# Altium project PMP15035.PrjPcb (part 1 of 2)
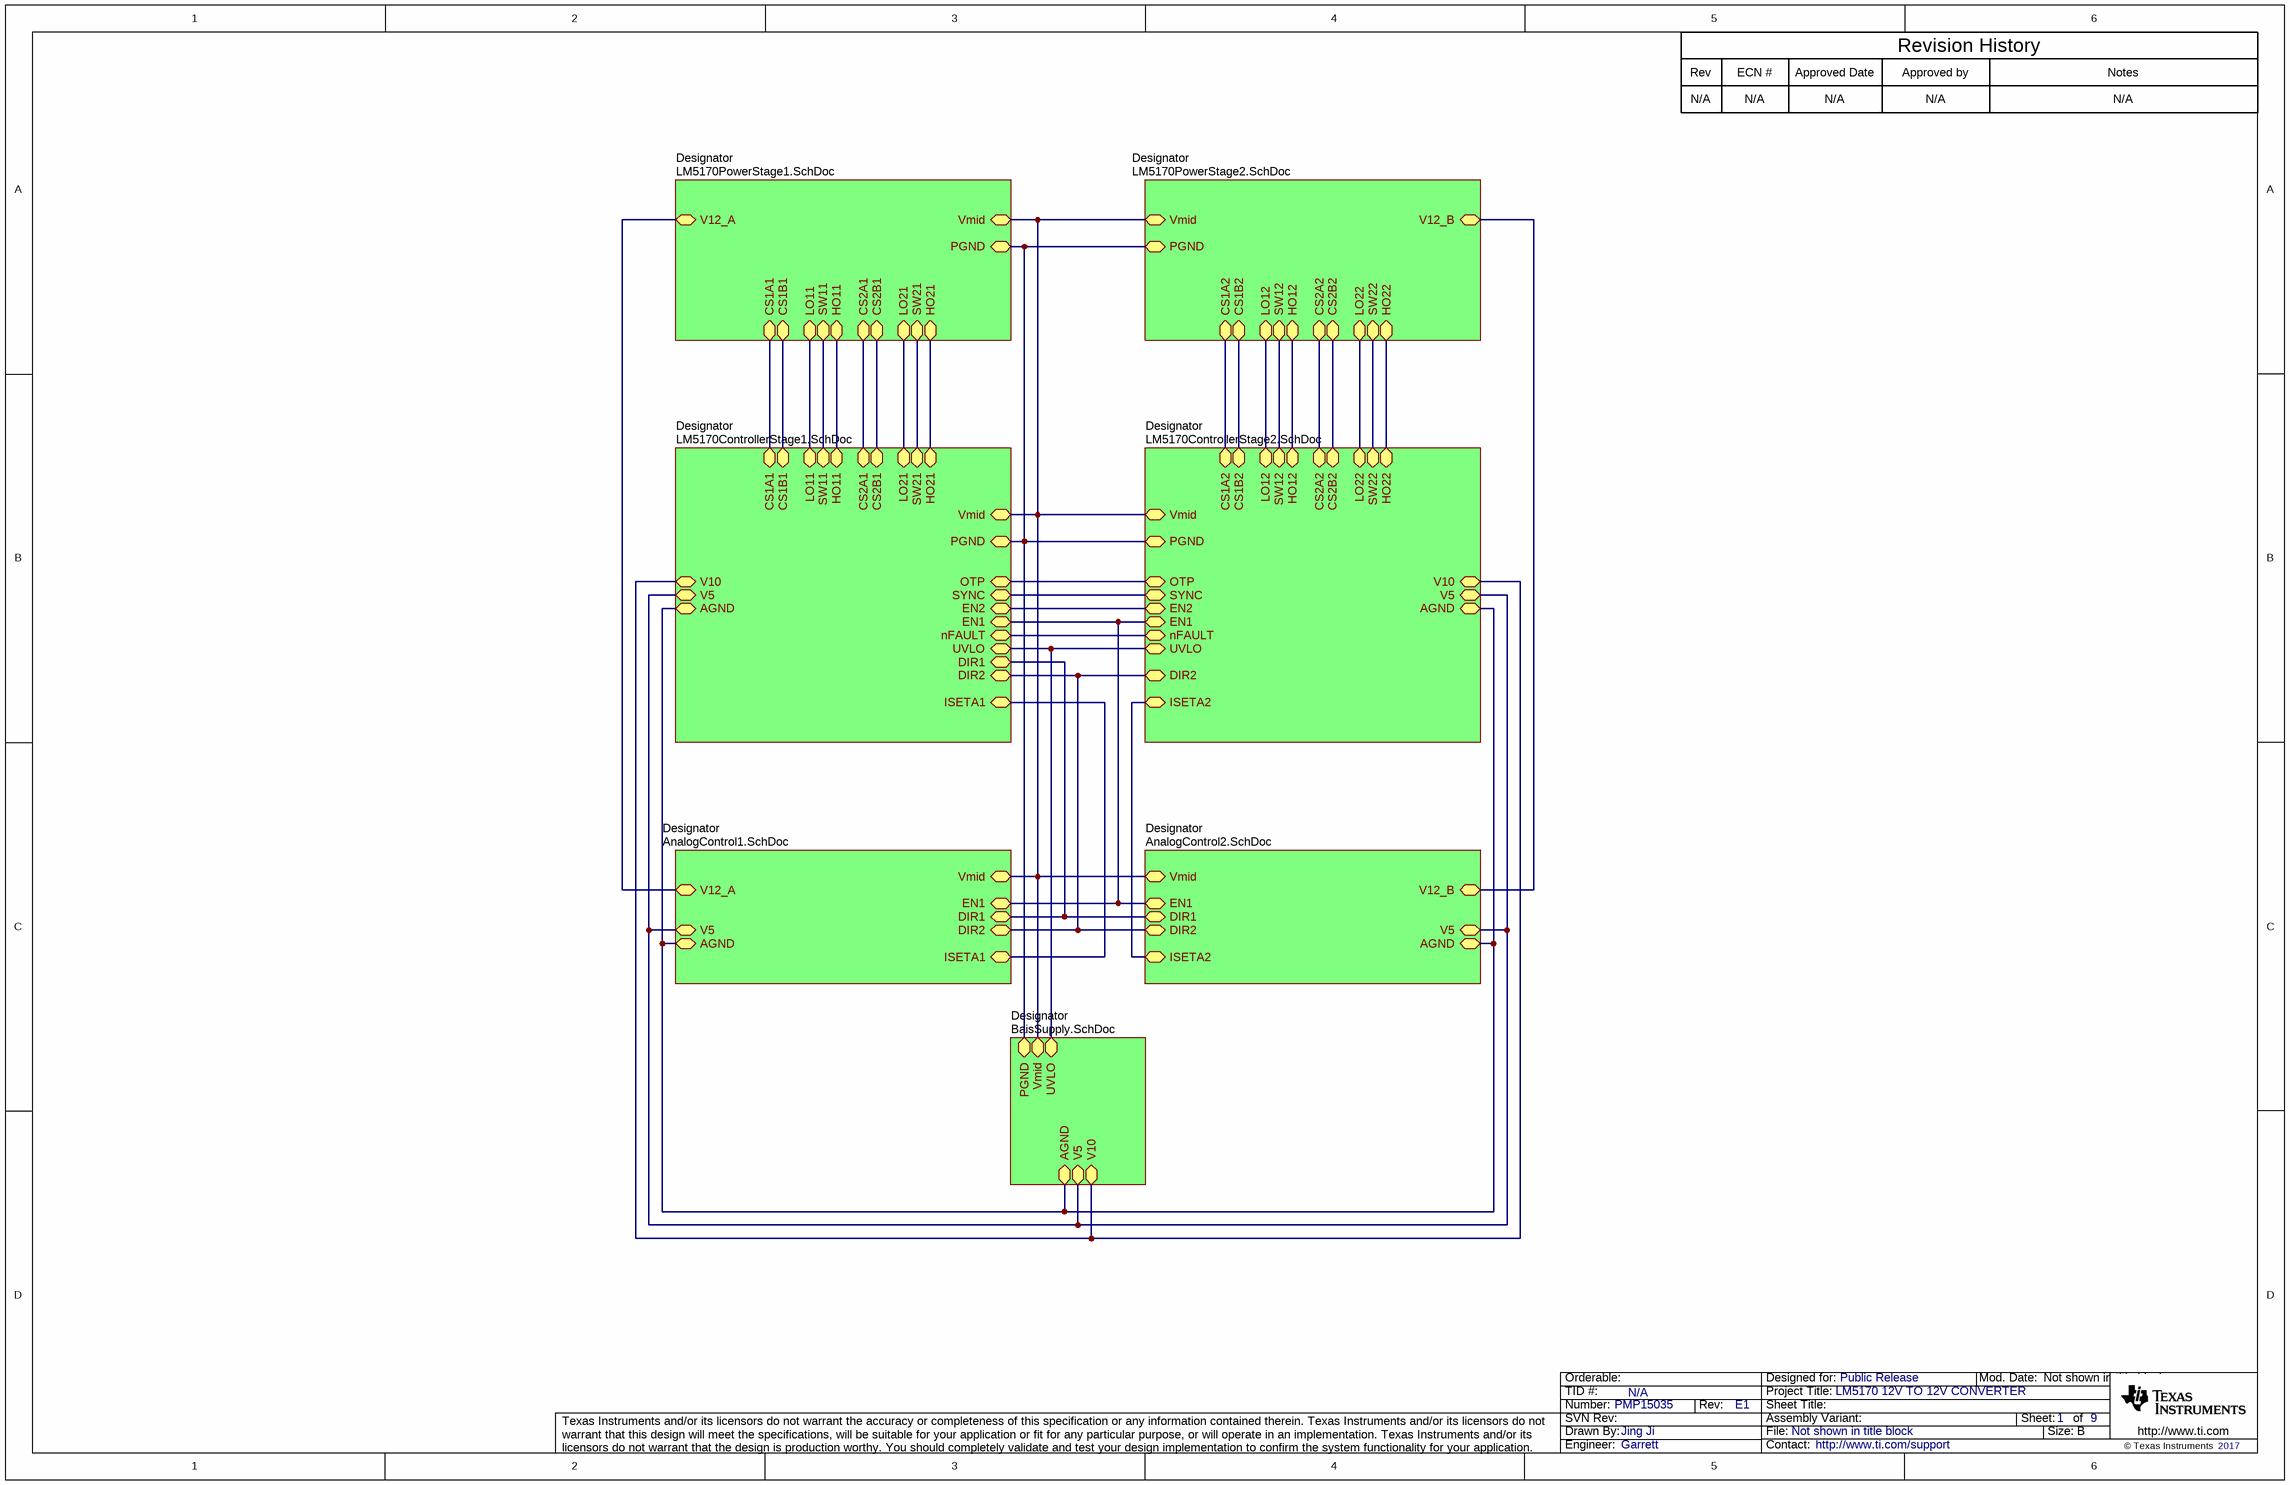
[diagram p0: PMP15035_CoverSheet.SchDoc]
CopyrightYear: 2017; PCB_Layout: Jing Ji; PCB_Rev: E1; PRJ_Customer: Public Release; PRJ_Engineer: Garrett; PRJ_Number: PMP15035; PRJ_Title: LM5170 12V TO 12V CONVERTER; SCH_Rev: E1; TechSupport: http://www.ti.com/support; TID: N/A
8 sheets, 339 parts. Net scope: hierarchical (ports join the sheet entries above them; power ports are global).
Board file: PMP15035_PCB.PcbDoc
Sheets:
  PMP15035_CoverSheet.SchDoc
    Designator = AnalogControl2.SchDoc
    Designator = LM5170PowerStage2.SchDoc
    Designator = LM5170PowerStage1.SchDoc
    Designator = AnalogControl1.SchDoc
    Designator = LM5170ControllerStage1.SchDoc
    Designator = LM5170ControllerStage2.SchDoc
    Designator = BaisSupply.SchDoc

## Sheet PMP15035_CoverSheet.SchDoc
size 431 x 279 mm; Date: Not shown in title block; ApprovedBy: Not shown in title block; CheckedBy: Not shown in title block; Author: Not shown in title block; CompanyName: Not shown in title block; DrawnBy: Jing Ji; Engineer: Not shown in title block; Organization: Not shown in title block; Address1: Not shown in title block; Address2: Not shown in title block; Address3: Not shown in title block; Address4: Not shown in title block; DocumentNumber: 1; Revision: Use project parameter SCH_Rev; SheetNumber: 1; SheetTotal: 9; PageSetup: Record=PageOptions¦CenterHorizontal=True¦CenterVertical=True¦PrintScale=1.00¦XCorrection=1.00¦YCorrection=1.00¦PrintKind=0¦BorderSize=5000000¦LeftOffset=0¦BottomOffset=0¦Orientation=2¦PaperLength=1000¦PaperWidth=1000¦Scale=100¦PaperSource=15¦PrintQuality=600¦MediaType=1¦DitherType=10¦PaperKind=Letter¦PrintScaleMode=1

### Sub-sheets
Designator = AnalogControl2.SchDoc: Vmid, V12_B, AGND, V5, DIR2, ISETA2, DIR1, EN1
Designator = LM5170PowerStage2.SchDoc: V12_B, Vmid, PGND, CS1A2, CS1B2, LO12, SW12, HO12, CS2A2, CS2B2, LO22, SW22, HO22
Designator = LM5170PowerStage1.SchDoc: Vmid, V12_A, PGND, CS1A1, CS1B1, LO11, SW11, HO11, CS2A1, CS2B1, LO21, SW21, HO21
Designator = AnalogControl1.SchDoc: Vmid, V12_A, AGND, V5, DIR1, ISETA1, DIR2, EN1
Designator = LM5170ControllerStage1.SchDoc: CS1A1, CS1B1, LO11, SW11, HO11, CS2A1, CS2B1, LO21, SW21, HO21, Vmid, PGND, V10, AGND, DIR1, ISETA1, DIR2, nFAULT, EN1, EN2, UVLO, SYNC, V5, OTP
Designator = LM5170ControllerStage2.SchDoc: CS1A2, CS1B2, LO12, SW12, HO12, CS2A2, CS2B2, LO22, SW22, HO22, Vmid, PGND, V10, AGND, DIR2, ISETA2, nFAULT, EN1, EN2, SYNC, UVLO, V5, OTP
Designator = BaisSupply.SchDoc: V10, AGND, PGND, Vmid, V5, UVLO

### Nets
AGND: sheet Designator/AGND, sheet Designator/AGND, sheet Designator/AGND, sheet Designator/AGND, sheet Designator/AGND
DIR1: sheet Designator/DIR1, sheet Designator/DIR1, sheet Designator/DIR1
EN1: sheet Designator/EN1, sheet Designator/EN1, sheet Designator/EN1, sheet Designator/EN1
EN2: sheet Designator/EN2, sheet Designator/EN2
nFAULT: sheet Designator/nFAULT, sheet Designator/nFAULT
PGND: sheet Designator/PGND, sheet Designator/PGND, sheet Designator/PGND, sheet Designator/PGND, sheet Designator/PGND
V5: sheet Designator/V5, sheet Designator/V5, sheet Designator/V5, sheet Designator/V5, sheet Designator/V5
V12_A: sheet Designator/V12_A, sheet Designator/V12_A
V12_B: sheet Designator/V12_B, sheet Designator/V12_B
VCC1: sheet Designator/V10, sheet Designator/V10, sheet Designator/V10
Vmid: sheet Designator/Vmid, sheet Designator/Vmid, sheet Designator/Vmid, sheet Designator/Vmid, sheet Designator/Vmid, sheet Designator/Vmid, sheet Designator/Vmid
CS1A1: sheet Designator/CS1A1, sheet Designator/CS1A1
CS1A2: sheet Designator/CS1A2, sheet Designator/CS1A2
CS1B1: sheet Designator/CS1B1, sheet Designator/CS1B1
CS1B2: sheet Designator/CS1B2, sheet Designator/CS1B2
CS2A1: sheet Designator/CS2A1, sheet Designator/CS2A1
CS2A2: sheet Designator/CS2A2, sheet Designator/CS2A2
CS2B1: sheet Designator/CS2B1, sheet Designator/CS2B1
CS2B2: sheet Designator/CS2B2, sheet Designator/CS2B2
DIR2: sheet Designator/DIR2, sheet Designator/DIR2, sheet Designator/DIR2, sheet Designator/DIR2
HO11: sheet Designator/HO11, sheet Designator/HO11
HO12: sheet Designator/HO12, sheet Designator/HO12
HO21: sheet Designator/HO21, sheet Designator/HO21
HO22: sheet Designator/HO22, sheet Designator/HO22
ISETA1: sheet Designator/ISETA1, sheet Designator/ISETA1
ISETA2: sheet Designator/ISETA2, sheet Designator/ISETA2
LO11: sheet Designator/LO11, sheet Designator/LO11
LO12: sheet Designator/LO12, sheet Designator/LO12
LO21: sheet Designator/LO21, sheet Designator/LO21
LO22: sheet Designator/LO22, sheet Designator/LO22
OTP: sheet Designator/OTP, sheet Designator/OTP
SW11: sheet Designator/SW11, sheet Designator/SW11
SW12: sheet Designator/SW12, sheet Designator/SW12
SW21: sheet Designator/SW21, sheet Designator/SW21
SW22: sheet Designator/SW22, sheet Designator/SW22
SYNC: sheet Designator/SYNC, sheet Designator/SYNC
UVLO: sheet Designator/UVLO, sheet Designator/UVLO, sheet Designator/UVLO

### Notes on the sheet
- Rev
- N/A
- ECN #
- Approved Date
- Approved by
- Revision History
- Notes

## Sheet AnalogControl2.SchDoc
size 431 x 279 mm; Date: Not shown in title block; ApprovedBy: Not shown in title block; CheckedBy: Not shown in title block; Author: Not shown in title block; CompanyName: Not shown in title block; Engineer: Not shown in title block; Organization: Not shown in title block; Address1: Not shown in title block; Address2: Not shown in title block; Address3: Not shown in title block; Address4: Not shown in title block; DocumentNumber: 7; Revision: Use project parameter SCH_Rev; SheetNumber: 7; SheetTotal: 9; PageSetup: Record=PageOptions¦CenterHorizontal=True¦CenterVertical=True¦PrintScale=1.00¦XCorrection=1.00¦YCorrection=1.00¦PrintKind=0¦BorderSize=5000000¦LeftOffset=0¦BottomOffset=0¦Orientation=2¦PaperLength=1000¦PaperWidth=1000¦Scale=100¦PaperSource=15¦PrintQuality=600¦MediaType=1¦DitherType=10¦PaperKind=Letter¦PrintScaleMode=1
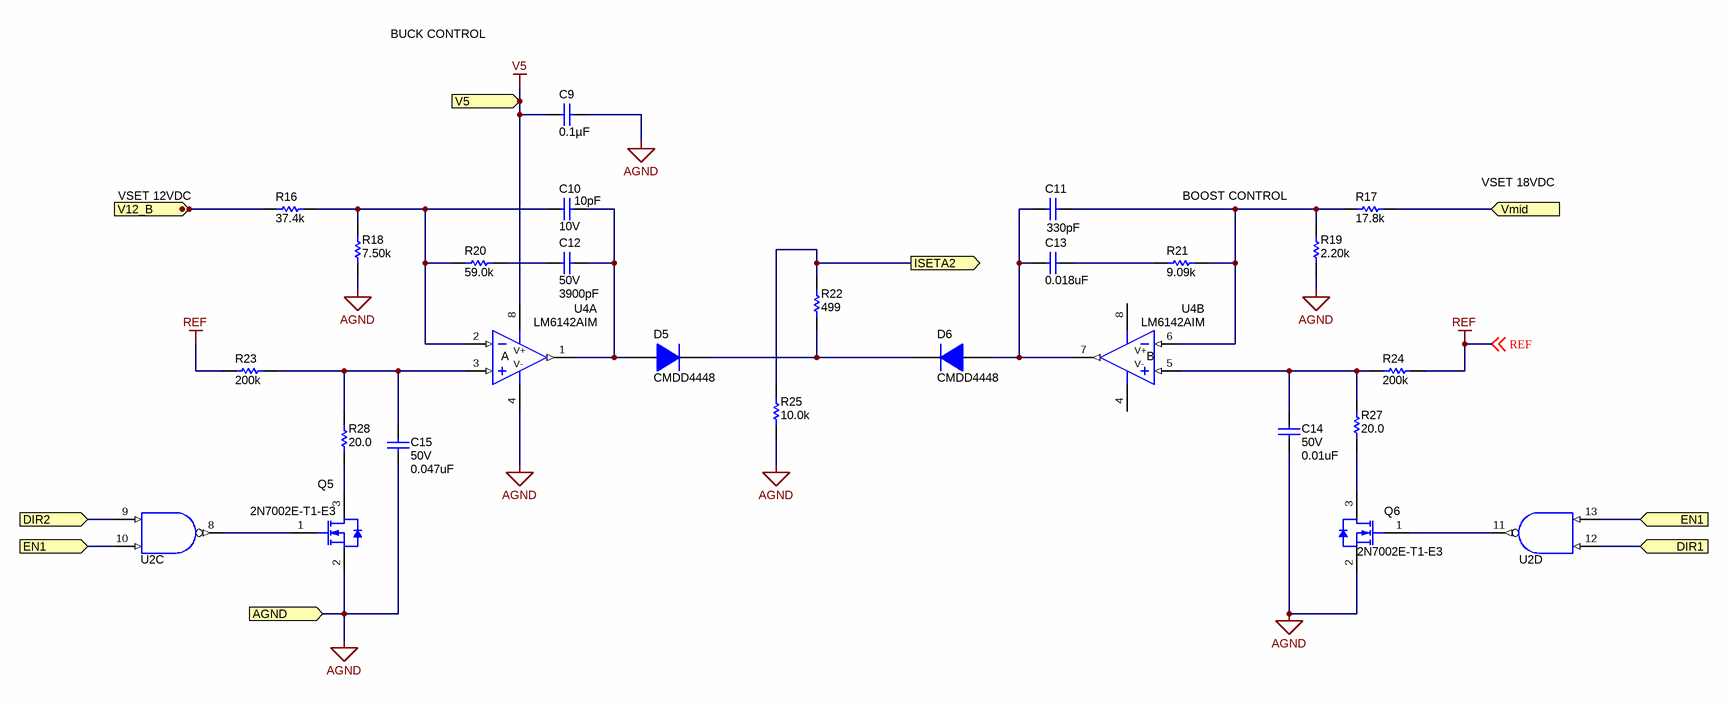
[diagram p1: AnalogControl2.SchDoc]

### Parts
C9  ValueDisplayed: 0.1µF  [0603L]  (hidden comment: GRM188R72A104KA35D)
C10  VDC_V: 10V  ValueDisplayed: 10pF  [0603]  (hidden comment: 0603ZC100KAT2A)
C11  ValueDisplayed: 330pF  [0603]  (hidden comment: C0603C331J5GACTU)
C12  VDC_V: 50V  ValueDisplayed: 3900pF  [0603]  (hidden comment: GRM188R71H392KA01D)
C13  ValueDisplayed: 0.018uF  [0603]  (hidden comment: GRM188R71H183KA01D)
C14  VDC_V: 50V  ValueDisplayed: 0.01uF  [0805_HV]  (hidden comment: 885012207092)
C15  VDC_V: 50V  ValueDisplayed: 0.047uF  [0805_HV]  (hidden comment: 08055C473KAT2A)
D5  CMDD4448  [sod-323]
D6  CMDD4448  [sod-323]
Q5  2N7002E-T1-E3  [SOT-23]
Q6  2N7002E-T1-E3  [SOT-23]
R16  ValueDisplayed: 37.4k  [0603L]  (hidden comment: CRCW060337K4FKEA)
R17  ValueDisplayed: 17.8k  [0603L]  (hidden comment: RC0603FR-0717K8L)
R18  ValueDisplayed: 7.50k  [0603]  (hidden comment: RC0603FR-077K5L)
R19  ValueDisplayed: 2.20k  [0603]  (hidden comment: RC0603FR-072K2L)
R20  ValueDisplayed: 59.0k  [0603]  (hidden comment: RC0603FR-0759KL)
R21  ValueDisplayed: 9.09k  [0603]  (hidden comment: RC0603FR-079K09L)
R22  ValueDisplayed: 499  [0603]  (hidden comment: RC0603FR-07499RL)
R23  ValueDisplayed: 200k  [0603]  (hidden comment: RC0603FR-07200KL)
R24  ValueDisplayed: 200k  [0603]  (hidden comment: RC0603FR-07200KL)
R25  ValueDisplayed: 10.0k  [0603L]  (hidden comment: CRCW060310K0FKEA)
R27  ValueDisplayed: 20.0  [0603L]  (hidden comment: CRCW060320R0FKEA)
R28  ValueDisplayed: 20.0  [0603L]  (hidden comment: CRCW060320R0FKEA)
U2  SN74LV00ADR  [D0014A_N]  (value not drawn)  (parts C,D of 5)
U4  LM6142AIM  [D0008A_N]  (parts A,B of 2)

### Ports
AGND, DIR1, DIR2, EN1, ISETA2, V5, V12_B, Vmid

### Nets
AGND: C9.2 C14.2 C15.2 Q5.2(S) Q6.2(S) R18.1 R19.1 R25.2 U4.4(V-) ; port AGND
DIR1: U2.12(4A) ; port DIR1
EN1: U2.10(3B) U2.13(4B) ; port EN1
REF: R23.2 R24.1 ; off-sheet REF
V5: C9.1 U4.8(V+) ; port V5
V12_B: R16.1 ; port V12_B
Vmid: R17.2 ; port Vmid
DIR2: U2.9(3A) ; port DIR2
ISETA2: R22.2 R25.1 ; port ISETA2
NetC10_1: C10.1 C12.1 D5.2(A) U4.1(OUT)
NetC10_2: C10.2 R16.2 R18.2 R20.2 U4.2(IN-)
NetC11_1: C11.1 R17.1 R19.2 R21.1 U4.6(IN-)
NetC11_2: C11.2 C13.1 D6.2(A) U4.7(OUT)
NetC12_2: C12.2 R20.1
NetC13_2: C13.2 R21.2
NetC14_1: C14.1 R24.2 R27.2 U4.5(IN+)
NetC15_1: C15.1 R23.1 R28.2 U4.3(IN+)
NetD5_1: D5.1(K) D6.1(K) R22.1
NetQ5_1: Q5.1(G) U2.8(3Y)
NetQ5_3: Q5.3(D) R28.1
NetQ6_1: Q6.1(G) U2.11(4Y)
NetQ6_3: Q6.3(D) R27.1

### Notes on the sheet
- BUCK CONTROL
- VSET 12VDC
- BOOST CONTROL
- VSET 18VDC

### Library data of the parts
C9 = GRM188R72A104KA35D: CAP, CERM, 0.1 µF, 100 V, +/- 10%, X7R, 0603; Manufacturer: MuRata; Polarized: N; CompType: Capacitor; Value: 0.1uF; U/M: EA; Cap_F: 0.0000001; Tolerance_%: 10; Value1: Unknown; VDC_V: 100; Value2: 100V; TaMin_C: -55; TaMax_C: 125; Cap_Case: 0603; AEC Category: Q200
C10 = CMP-0006811-4: CAP, CERM, 10 pF, 10 V, +/- 10%, X7R, 0603; Manufacturer: AVX; TaMin_C: -55°C; Polarized: N; SizeAreaWB_mm2: 4.68; Value1: Unknown; U/M: EA; Value: 10pF; TaMax_C: 125°C; SizeZ_mm: 1; SizeX_mm: 1.6; SizeY_mm: 0.8; SizeArea_mm2: 1.28; CompType: Capacitor; AEC Category: Q200
C11 = CMP-0006920-4: CAP, CERM, 330 pF, 50 V, +/- 5%, C0G/NP0, 0603; Manufacturer: Kemet; TaMin_C: -55°C; Polarized: N; SizeAreaWB_mm2: 4.68; Value1: Unknown; U/M: EA; Value: 330pF; TaMax_C: 125°C; SizeZ_mm: 1; SizeX_mm: 1.6; SizeY_mm: 0.8; Value2: 50V; SizeArea_mm2: 1.28; CompType: Capacitor; AEC Category: Q200
C12 = CMP-0007453-4: CAP, CERM, 3900 pF, 50 V, +/- 10%, X7R, 0603; Manufacturer: MuRata; TaMin_C: -55°C; Polarized: N; SizeAreaWB_mm2: 4.68; Value1: Unknown; U/M: EA; Value: 3900pF; TaMax_C: 125°C; SizeZ_mm: 1; SizeX_mm: 1.6; SizeY_mm: 0.8; SizeArea_mm2: 1.28; CompType: Capacitor; Cap_F: 3.9nF; AEC Category: Q200
C13 = CMP-0007440-5: CAP, CERM, 0.018 uF, 50 V, +/- 10%, X7R, 0603; Manufacturer: MuRata; TaMin_C: -55°C; Polarized: N; SizeAreaWB_mm2: 4.68; Value1: Unknown; U/M: EA; TaMax_C: 125°C; SizeZ_mm: 1; SizeX_mm: 1.6; SizeY_mm: 0.8; Value2: 50V; SizeArea_mm2: 1.28; CompType: Capacitor; Cap_F: 18nF; AEC Category: Q200
C14 = CMP-0007694-2: CAP, CERM, 0.01 uF, 50 V, +/- 10%, X7R, 0805; Manufacturer: Wurth Elektronik; TaMin_C: -55°C; Polarized: N; SizeAreaWB_mm2: 6.75; Value1: Unknown; U/M: EA; Value: 0.01uF; TaMax_C: 125°C; SizeZ_mm: 1.45; SizeX_mm: 2; SizeY_mm: 1.25; Cap_Case: 0805; SizeArea_mm2: 2.5; CompType: Capacitor; Cap_F: 10nF; AEC Category: Q200
C15 = CMP-0007659-2: CAP, CERM, 0.047 uF, 50 V, +/- 10%, X7R, 0805; Manufacturer: AVX; TaMin_C: -55°C; ESR_ohm: 0.035; Polarized: N; SizeAreaWB_mm2: 6.75; Value1: 0.035 ohm; U/M: EA; TaMax_C: 125°C; SizeZ_mm: 1.45; SizeX_mm: 2; SizeY_mm: 1.25; Cap_Case: 0805; SizeArea_mm2: 2.5; CompType: Capacitor; Cap_F: 47nF; AEC Category: Q200
D5 D6 = CMDD4448: Diode, Ultrafast, 75 V, 0.25 A, SOD-323; Manufacturer: Central Semiconductor; U/M: EA; Vf_V: 1.2; Value: 75V; Value1: 0.25A; Value2: 1.2V; Io_A: 0.25; Vr_V: 75; TJmax_C: 175
Q5 Q6 = 2N7002E-T1-E3: MOSFET, N-CH, 60 V, 0.24 A, SOT-23; Manufacturer: Vishay-Siliconix; Alternate Manufacturer: None; U/M: EA; ChType: N; Value: 60V; VdsMax_V: 60; Value1: 1.8 ohm; Rdson45_ohm: 1.8; Value2: 0.4 nC; QgTyp_nC: 0.4; Vgs_V: 20; IdsMax_A: 0.24
R16 = CMP-0022360-3: RES, 37.4 k, 1%, 0.1 W, 0603; Manufacturer: Vishay-Dale; Power_W: 100mW; TempCo: 100 ppm/C; Value_Code: 37k4; U/M: EA; Value: 37.4k; EIA_Code: E96; SizeX_mm: 1.6; SizeY_mm: 0.8; SizeZ_mm: 1; Value2: 0.1W; SizeArea_mm2: 1.28; CompType: Resistor; VDC_V: 75V; AEC Category: Q200
R17 = CMP-0022841-3: RES, 17.8 k, 1%, 0.1 W, 0603; Manufacturer: Yageo America; Power_W: 100mW; TempCo: 200 ppm/C; Value_Code: 17k8; U/M: EA; Value: 17.8k; EIA_Code: E96; SizeX_mm: 1.6; SizeY_mm: 0.8; SizeZ_mm: 1; Value2: 0.1W; SizeArea_mm2: 1.28; CompType: Resistor; VDC_V: 150V; AEC Category: Q200
R18 = CMP-0023279-3: RES, 7.50 k, 1%, 0.1 W, 0603; Manufacturer: Yageo America; Power_W: 100mW; TempCo: 200 ppm/C; Value_Code: 7k50; U/M: EA; Value: 7.50k; EIA_Code: E96; Res_ohm: 7.5k; SizeX_mm: 1.6; SizeY_mm: 0.8; SizeZ_mm: 1; Value2: 0.1W; SizeArea_mm2: 1.28; CompType: Resistor; VDC_V: 150V; AEC Category: Q200
R19 = CMP-0022986-3: RES, 2.20 k, 1%, 0.1 W, 0603; Manufacturer: Yageo America; Power_W: 100mW; TempCo: 200 ppm/C; Value_Code: 2k20; U/M: EA; Value: 2.20k; Res_ohm: 2.2k; SizeX_mm: 1.6; SizeY_mm: 0.8; SizeZ_mm: 1; Value2: 0.1W; SizeArea_mm2: 1.28; CompType: Resistor; VDC_V: 150V; AEC Category: Q200
R20 = CMP-0023195-3: RES, 59.0 k, 1%, 0.1 W, 0603; Manufacturer: Yageo America; Power_W: 100mW; TempCo: 200 ppm/C; Value_Code: 59k0; U/M: EA; Value: 59.0k; EIA_Code: E96; Res_ohm: 59k; SizeX_mm: 1.6; SizeY_mm: 0.8; SizeZ_mm: 1; Value2: 0.1W; SizeArea_mm2: 1.28; CompType: Resistor; VDC_V: 150V; AEC Category: Q200
R21 = CMP-0023332-3: RES, 9.09 k, 1%, 0.1 W, 0603; Manufacturer: Yageo America; Power_W: 100mW; TempCo: 200 ppm/C; Value_Code: 9k09; U/M: EA; Value: 9.09k; EIA_Code: E96; SizeX_mm: 1.6; SizeY_mm: 0.8; SizeZ_mm: 1; Value2: 0.1W; SizeArea_mm2: 1.28; CompType: Resistor; VDC_V: 150V; AEC Category: Q200
R22 = CMP-0023141-3: RES, 499, 1%, 0.1 W, 0603; Manufacturer: Yageo America; Power_W: 100mW; TempCo: 200 ppm/C; Value_Code: 499R; U/M: EA; Value: 499; EIA_Code: E96; SizeX_mm: 1.6; SizeY_mm: 0.8; SizeZ_mm: 1; Value2: 0.1W; SizeArea_mm2: 1.28; CompType: Resistor; VDC_V: 150V; AEC Category: Q200
R23 R24 = CMP-0022901-2: RES, 200 k, 1%, 0.1 W, 0603; Manufacturer: Yageo America; Power_W: 100mW; TempCo: 200 ppm/C; U/M: EA; Value: 200k; EIA_Code: E96; SizeX_mm: 1.6; SizeY_mm: 0.8; SizeZ_mm: 1; Value2: 0.1W; CompType: Resistor; VDC_V: 150V; AEC Category: Q200; SizeArea_mm2: 1.28
R25 = CRCW060310K0FKEA: RES, 10.0 k, 1%, 0.1 W, 0603; Manufacturer: Vishay-Dale; CompType: Resistor; Value: 10.0k; Res_ohm: 10000; Value_Code: 10k0; Tolerance_%: 1; Power_W: 0.1; Value2: 0.1W; VDC_V: 75; TempCo: 100 ppm/C; EIA_Code: E96; U/M: EA
R27 R28 = CRCW060320R0FKEA: RES, 20.0, 1%, 0.1 W, 0603; Manufacturer: Vishay-Dale; CompType: Resistor; Value: 20.0; Res_ohm: 20; Value_Code: 20R0; Tolerance_%: 1; Power_W: 0.1; Value2: 0.1W; VDC_V: 75; TempCo: 100 ppm/C; EIA_Code: E96; U/M: EA
U2 = CMP-0052884-1: Quadruple 2-Input Positive-NAND Gates, D0014A, LARGE T&R; Manufacturer: Texas Instruments; Output Drive (IOL/IOH)(Max)(mA): 50/-50; Rating: Catalog; F @ Nom Voltage(Max)(Mhz): 70; tpd @ Nom Voltage(Max)(ns): 20,13,8.5; ICC @ Nom Voltage(Max)(mA): 0.02; Output Type: TTL; Technology Family: LV-A; Bits(#): 4; Schmitt Trigger: No; VCC(Min)(V): 2; Voltage(Nom)(V): 2.5,3.3,5; VCC(Max)(V): 5.5
U4 = LM6142AIM: 17MHz Rail-to-Rail Input and Output Op Amp, D0008A; Manufacturer: Texas Instruments; CompType: OpAmp IC

## Sheet LM5170PowerStage2.SchDoc
size 431 x 279 mm; Date: Not shown in title block; ApprovedBy: Not shown in title block; CheckedBy: Not shown in title block; Author: Not shown in title block; CompanyName: Not shown in title block; Engineer: Not shown in title block; Organization: Not shown in title block; Address1: Not shown in title block; Address2: Not shown in title block; Address3: Not shown in title block; Address4: Not shown in title block; DocumentNumber: 3; Revision: Use project parameter SCH_Rev; SheetNumber: 3; SheetTotal: 9; PageSetup: Record=PageOptions¦CenterHorizontal=True¦CenterVertical=True¦PrintScale=1.00¦XCorrection=1.00¦YCorrection=1.00¦PrintKind=0¦BorderSize=5000000¦LeftOffset=0¦BottomOffset=0¦Orientation=2¦PaperLength=1000¦PaperWidth=1000¦Scale=100¦PaperSource=15¦PrintQuality=600¦MediaType=1¦DitherType=10¦PaperKind=Letter¦PrintScaleMode=1
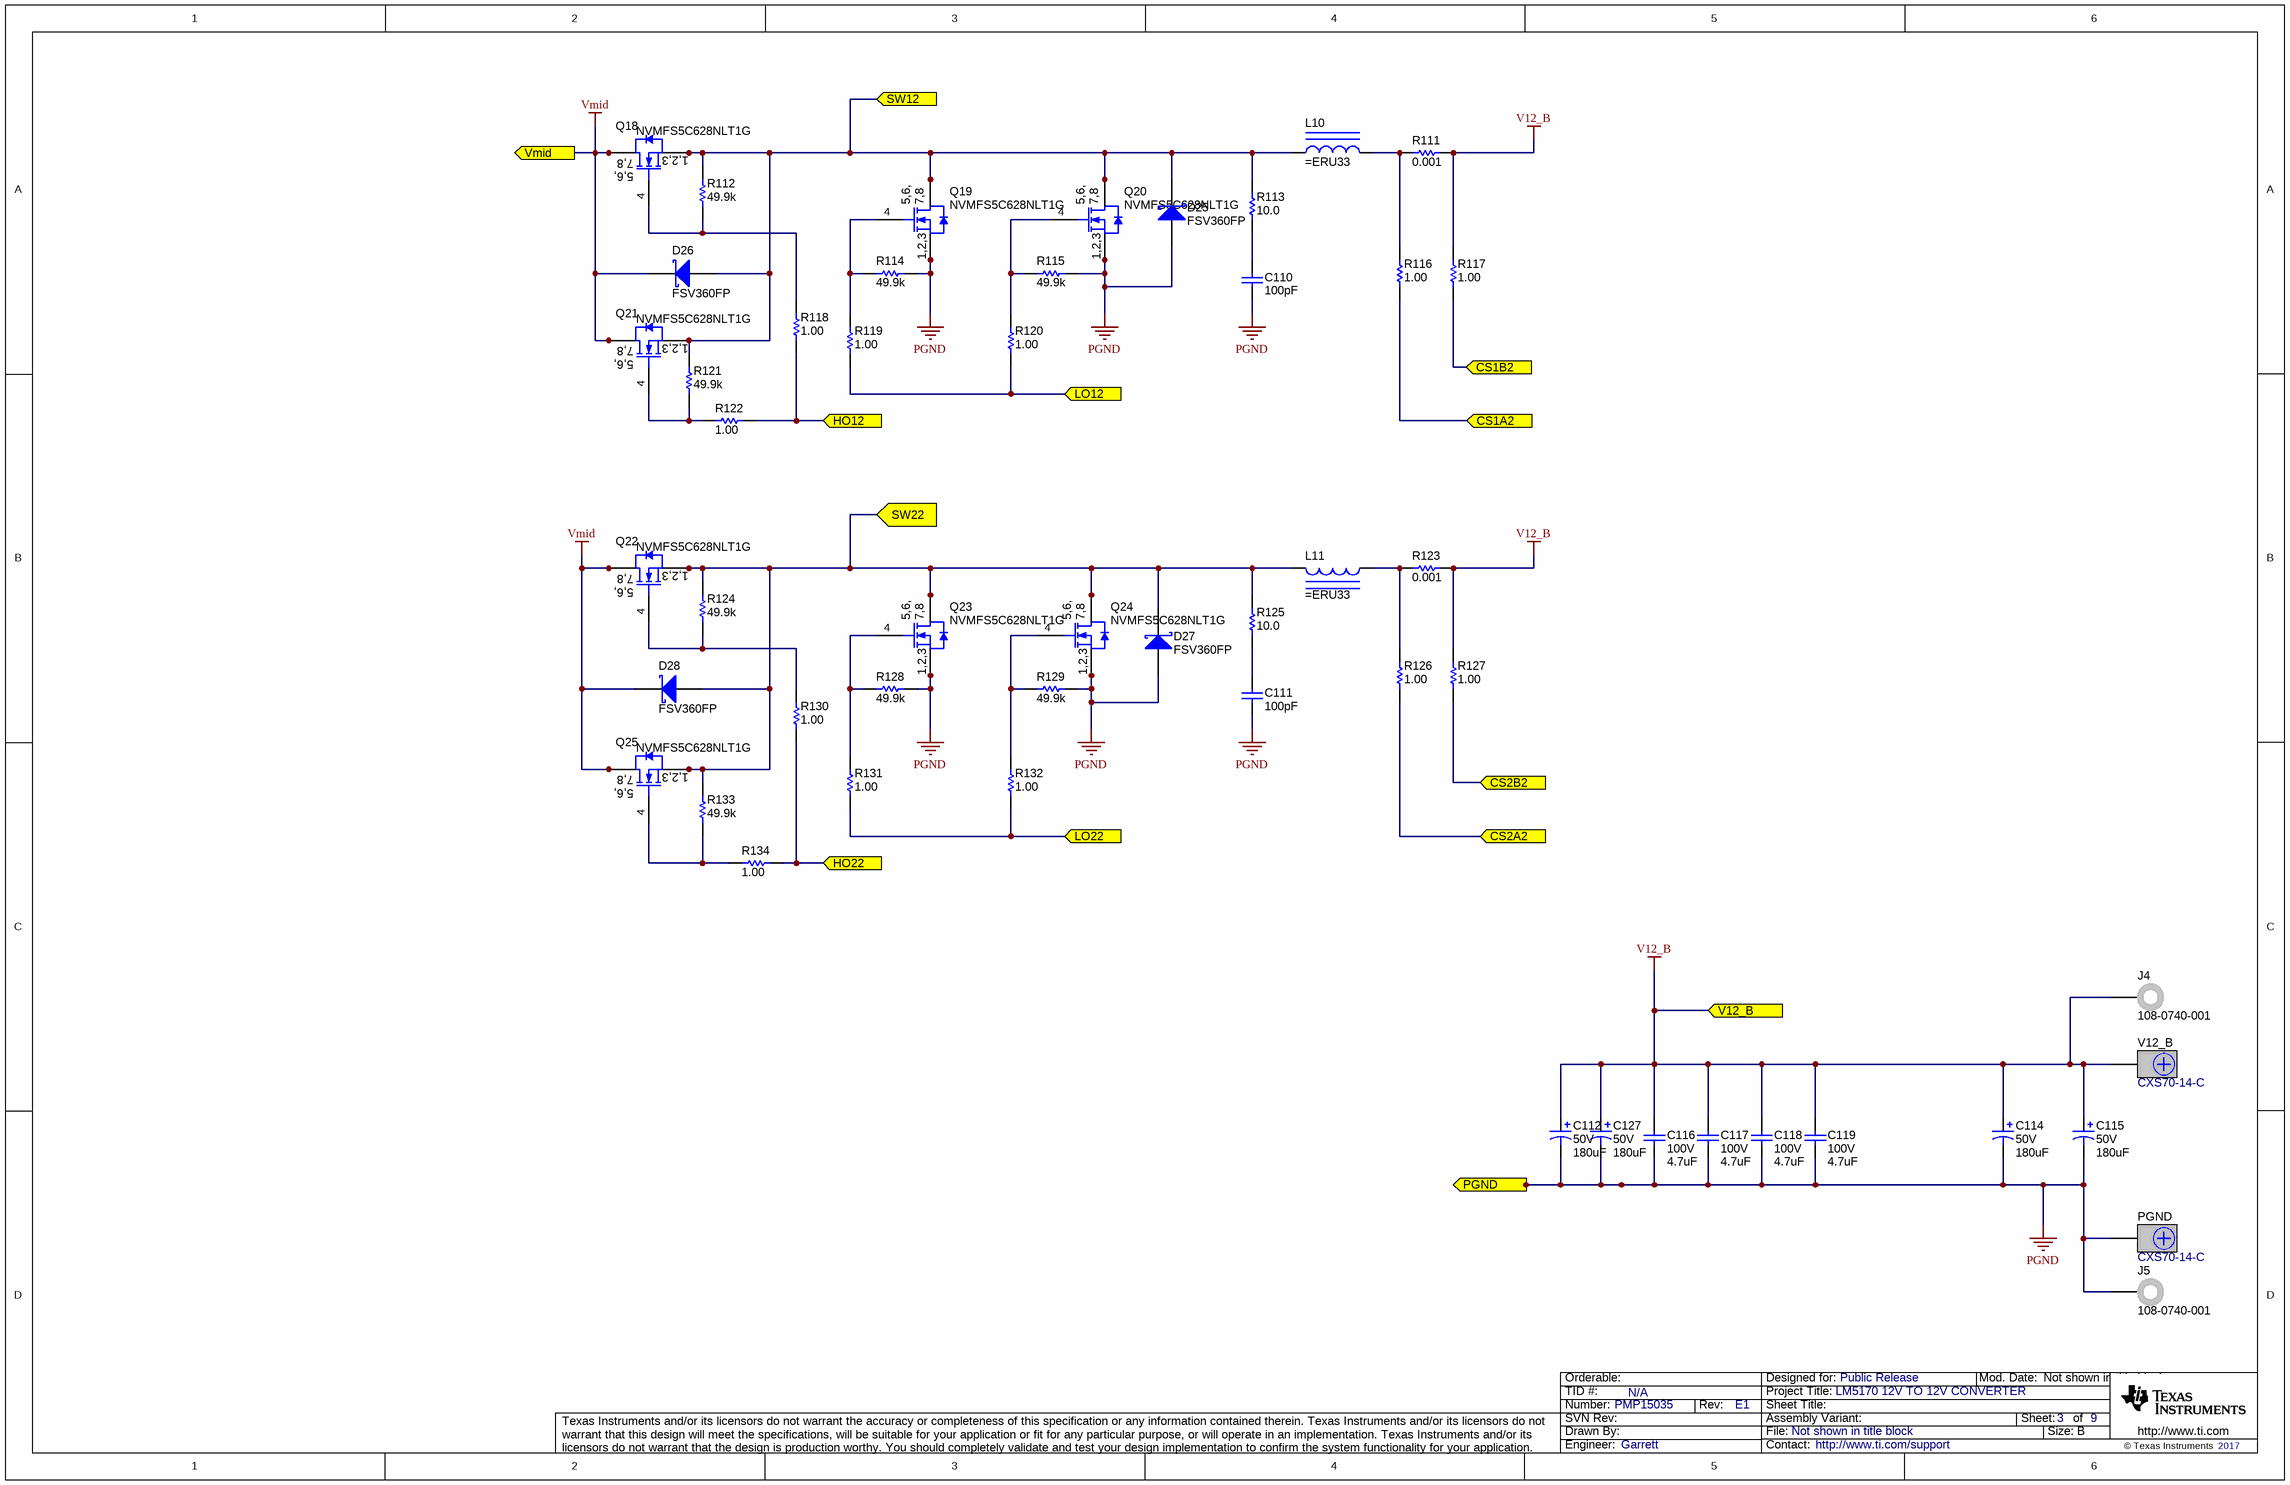
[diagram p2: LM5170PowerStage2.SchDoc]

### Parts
(Parts that share a designator on the sheet are numbered #1, #2 ... from top to bottom, then left to right.)
C110  ValueDisplayed: 100pF  [0805_HV]  (hidden comment: 08051A101KAT2A)
C111  ValueDisplayed: 100pF  [0805_HV]  (hidden comment: 08051A101KAT2A)
C112  VDC_V: 50V  ValueDisplayed: 180uF  [CR_1000x1270]  (hidden comment: PCR1H181MCL1GS)
C114  VDC_V: 50V  ValueDisplayed: 180uF  [CR_1000x1270]  (hidden comment: PCR1H181MCL1GS)
C115  VDC_V: 50V  ValueDisplayed: 180uF  [CR_1000x1270]  (hidden comment: PCR1H181MCL1GS)
C116  VDC_V: 100V  ValueDisplayed: 4.7uF  [2220_280]  (hidden comment: C5750X7R2A475M230KA)
C117  VDC_V: 100V  ValueDisplayed: 4.7uF  [2220_280]  (hidden comment: C5750X7R2A475M230KA)
C118  VDC_V: 100V  ValueDisplayed: 4.7uF  [2220_280]  (hidden comment: C5750X7R2A475M230KA)
C119  VDC_V: 100V  ValueDisplayed: 4.7uF  [2220_280]  (hidden comment: C5750X7R2A475M230KA)
C127  VDC_V: 50V  ValueDisplayed: 180uF  [CR_1000x1270]  (hidden comment: PCR1H181MCL1GS)
D25  FSV360FP  [SOD-123HE]
D26  FSV360FP  [SOD-123HE]
D27  FSV360FP  [SOD-123HE]
D28  FSV360FP  [SOD-123HE]
J4  108-0740-001  [Johnson_108-0740-001]  (mechanical)
J5  108-0740-001  [Johnson_108-0740-001]  (mechanical)
L10  (no value)  [ERU33]
L11  (no value)  [ERU33]
PGND#1  CXS70-14-C  [Panduit_CXS70-14-C]
Q18  NVMFS5C628NLT1G  [PG-TDSON-8]
Q19  NVMFS5C628NLT1G  [PG-TDSON-8]
Q20  NVMFS5C628NLT1G  [PG-TDSON-8]
Q21  NVMFS5C628NLT1G  [PG-TDSON-8]
Q22  NVMFS5C628NLT1G  [PG-TDSON-8]
Q23  NVMFS5C628NLT1G  [PG-TDSON-8]
Q24  NVMFS5C628NLT1G  [PG-TDSON-8]
Q25  NVMFS5C628NLT1G  [PG-TDSON-8]
R111  ValueDisplayed: 0.001  [CSS2725_001]  (hidden comment: CSS2725FT1L00)
R112  ValueDisplayed: 49.9k  [0603]  (hidden comment: CRCW060349K9FKEA)
R113  ValueDisplayed: 10.0  [1218]  (hidden comment: CRCW121810R0FKEK)
R114  ValueDisplayed: 49.9k  [0603]  (hidden comment: CRCW060349K9FKEA)
R115  ValueDisplayed: 49.9k  [0603]  (hidden comment: CRCW060349K9FKEA)
R116  ValueDisplayed: 1.00  [0603]  (hidden comment: RC0603FR-071RL)
R117  ValueDisplayed: 1.00  [0603]  (hidden comment: RC0603FR-071RL)
R118  ValueDisplayed: 1.00  [0805_HV]  (hidden comment: CRCW08051R00FKEA)
R119  ValueDisplayed: 1.00  [0805_HV]  (hidden comment: CRCW08051R00FKEA)
R120  ValueDisplayed: 1.00  [0805_HV]  (hidden comment: CRCW08051R00FKEA)
R121  ValueDisplayed: 49.9k  [0603]  (hidden comment: CRCW060349K9FKEA)
R122  ValueDisplayed: 1.00  [0805_HV]  (hidden comment: CRCW08051R00FKEA)
R123  ValueDisplayed: 0.001  [CSS2725_001]  (hidden comment: CSS2725FT1L00)
R124  ValueDisplayed: 49.9k  [0603]  (hidden comment: CRCW060349K9FKEA)
R125  ValueDisplayed: 10.0  [1218]  (hidden comment: CRCW121810R0FKEK)
R126  ValueDisplayed: 1.00  [0603]  (hidden comment: RC0603FR-071RL)
R127  ValueDisplayed: 1.00  [0603]  (hidden comment: RC0603FR-071RL)
R128  ValueDisplayed: 49.9k  [0603]  (hidden comment: CRCW060349K9FKEA)
R129  ValueDisplayed: 49.9k  [0603]  (hidden comment: CRCW060349K9FKEA)
R130  ValueDisplayed: 1.00  [0805_HV]  (hidden comment: CRCW08051R00FKEA)
R131  ValueDisplayed: 1.00  [0805_HV]  (hidden comment: CRCW08051R00FKEA)
R132  ValueDisplayed: 1.00  [0805_HV]  (hidden comment: CRCW08051R00FKEA)
R133  ValueDisplayed: 49.9k  [0603]  (hidden comment: CRCW060349K9FKEA)
R134  ValueDisplayed: 1.00  [0805_HV]  (hidden comment: CRCW08051R00FKEA)
V12_B  CXS70-14-C  [Panduit_CXS70-14-C]

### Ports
CS1A2, CS1B2, CS2A2, CS2B2, HO12, HO22, LO12, LO22, PGND, SW12, SW22, V12_B, Vmid

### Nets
PGND: C110.2 C111.2 C112.2(-) C114.2(-) C115.2(-) C116.2 C117.2 C118.2 C119.2 C127.2(-) D25.2(A) D27.2(A) J5.1 PGND#1.1 Q19.1(S) Q19.2(S) Q19.3(S) Q20.1(S) Q20.2(S) Q20.3(S) Q23.1(S) Q23.2(S) Q23.3(S) Q24.1(S) Q24.2(S) Q24.3(S) R114.1 R115.1 R128.2 R129.2 ; port PGND
V12_B: C112.1(+) C114.1(+) C115.1(+) C116.1 C117.1 C118.1 C119.1 C127.1(+) J4.1 R111.2 R117.2 R123.2 R127.2 V12_B.1 ; port V12_B
Vmid: D26.1(K) D28.1(K) Q18.5(D) Q18.6(D) Q18.7(D) Q18.8(D) Q18.9(D) Q21.5(D) Q21.6(D) Q21.7(D) Q21.8(D) Q21.9(D) Q22.5(D) Q22.6(D) Q22.7(D) Q22.8(D) Q22.9(D) Q25.5(D) Q25.6(D) Q25.7(D) Q25.8(D) Q25.9(D) ; port Vmid
CS1A2: R116.1 ; port CS1A2
CS1B2: R117.1 ; port CS1B2
CS2A2: R126.1 ; port CS2A2
CS2B2: R127.1 ; port CS2B2
HO12: R118.1 R122.1 ; port HO12
HO22: R130.1 R134.1 ; port HO22
LO12: R119.1 R120.1 ; port LO12
LO22: R131.1 R132.1 ; port LO22
SW12: D25.1(K) D26.2(A) L10.1 Q18.1(S) Q18.2(S) Q18.3(S) Q19.5(D) Q19.6(D) Q19.7(D) Q19.8(D) Q19.9(D) Q20.5(D) Q20.6(D) Q20.7(D) Q20.8(D) Q20.9(D) Q21.1(S) Q21.2(S) Q21.3(S) R112.2 R113.2 R121.2 ; port SW12
SW22: D27.1(K) D28.2(A) L11.2 Q22.1(S) Q22.2(S) Q22.3(S) Q23.5(D) Q23.6(D) Q23.7(D) Q23.8(D) Q23.9(D) Q24.5(D) Q24.6(D) Q24.7(D) Q24.8(D) Q24.9(D) Q25.1(S) Q25.2(S) Q25.3(S) R124.2 R125.2 R133.2 ; port SW22
NetC110_1: C110.1 R113.1
NetC111_1: C111.1 R125.1
NetL10_2: L10.2 R111.1 R116.2
NetL11_1: L11.1 R123.1 R126.2
NetQ18_4: Q18.4(G) R112.1 R118.2
NetQ19_4: Q19.4(G) R114.2 R119.2
NetQ20_4: Q20.4(G) R115.2 R120.2
NetQ21_4: Q21.4(G) R121.1 R122.2
NetQ22_4: Q22.4(G) R124.1 R130.2
NetQ23_4: Q23.4(G) R128.1 R131.2
NetQ24_4: Q24.4(G) R129.1 R132.2
NetQ25_4: Q25.4(G) R133.1 R134.2

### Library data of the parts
C110 C111 = 08051A101KAT2A: CAP, CERM, 100 pF, 100 V, +/- 10%, C0G/NP0, 0805; Manufacturer: AVX; Polarized: N; CompType: Capacitor; Value: 100pF; U/M: EA; Cap_F: 0.0000000001; Tolerance_%: 10; ESR_ohm: 0.356; Value1: 0.356 ohm; VDC_V: 100; Value2: 100V; TaMin_C: -55; TaMax_C: 125; Cap_Case: 0805
C112 C114 C115 C127 = CMP-0012273-3: CAP, Aluminum Polymer, 180 uF, 50 V, +/- 20%, 0.019 ohm, SMD, 2-Leads, Dia 10.5mm, Pin Spacing 8mm SMD; Manufacturer: Nichicon; TaMin_C: -55°C; ESR_ohm: 0.019; Polarized: Y; Value: 180uF; TaMax_C: 125°C; Cap_Case: 10x12.7mm; CompType: Capacitor; AEC Qualified: N; Cap_F: 180µF; IRMS_A: 3.5A; AEC Category: Q200
C116-C119 = CMP-0009385-2: CAP, CERM, 4.7 uF, 100 V, +/- 20%, X7R, 2220; Manufacturer: TDK; TaMin_C: -55°C; ESR_ohm: 1.5m; Polarized: N; SizeAreaWB_mm2: 53.9; Value1: 0.0015 ohm; U/M: EA; Value: 4.7uF; TaMax_C: 125°C; SizeZ_mm: 2.8; SizeX_mm: 5.7; SizeY_mm: 5; Cap_Case: 2220; SizeArea_mm2: 28.5; CompType: Capacitor; Cap_F: 4.7µF; IRMS_A: 5.5A; AEC Category: Q200
D25-D28 = CMP-0028825-1: Diode, Schottky, 60 V, 3 A, AEC-Q101, SOD-123HE; Manufacturer: Fairchild Semiconductor; Io_A: 3A; Green_Lifecycle: Not Set; SizeAreaWB_mm2: 13.16; Vr_V: 60V; Green_REACh: Incomplete; TJmax_C: 150°C; U/M: EA; Value: 60V; SizeZ_mm: 1; SizeX_mm: 3.7; SizeY_mm: 1.8; Vf_V: 6.5dV; Value2: 0.65V; SizeArea_mm2: 6.66; AEC Qualified: Y; AEC Category: Q101
J4 J5 = 108-0740-001: Standard Banana Jack, Uninsulated, 15A; Manufacturer: Emerson Network Power; SymbolCreator: a0412235; CompType: Connector; U/M: EA
L10 L11 = ERU33: Manufacturer: Used in BOM report; SymbolVersion: use current date i.e. 2008-05-20; SymbolCreator: Use a-id; CompType: Used in some BOM reports.  Useful for finding later.; U/M: EA, IN, or GM
PGND#1 V12_B = CXS70-14-C: Terminal 70A Lug; Manufacturer: Panduit; SymbolCreator: crossc; CompType: Screw Terminal; U/M: EA
Q18-Q25 = NVMFS5C628NLT1G: MOSFET N-CH 60V SO8FL; Manufacturer: Used in BOM report; SymbolVersion: use current date i.e. 2008-05-20; SymbolCreator: Use a-id; CompType: Used in some BOM reports.  Useful for finding later.; U/M: EA, IN, or GM; Rds On Max: 2.4mR; Input Capacitance: 3.6nF; Max Power Dissipation: 3.7W
R111 R123 = CMP-0015025-2: RES, 0.001, 1%, 4 W, RES_2725; Manufacturer: Stackpole Electronics Inc; Power_W: 4W; TempCo: 50 ppm/C; Value_Code: 1L000; U/M: EA; Value: 0.001; EIA_Code: E96; Res_ohm: 1m; CompType: Resistor; AEC Category: Q200
R112 R114 R115 R121 R124 R128 R129 R133 = CMP-0022447-4: RES, 49.9 k, 1%, 0.1 W, AEC-Q200 Grade 0, 0603; Manufacturer: Vishay-Dale; Power_W: 100mW; TempCo: 100 ppm/C; Value_Code: 49k9; Value: 49.9k; EIA_Code: E96; SizeX_mm: 1.6; SizeY_mm: 0.8; SizeZ_mm: 1; Value2: 0.1W; SizeArea_mm2: 1.28; CompType: Resistor; AEC Qualified: Y; VDC_V: 75V; AEC Category: Q200; AEC Grade: 0
R113 R125 = CRCW121810R0FKEK: RES, 10.0, 1%, 1 W, 1218; Manufacturer: Vishay-Dale; CompType: Resistor; Value: 10.0; Res_ohm: 10; Value_Code: 10R0; Tolerance_%: 1; Value2: 1W; VDC_V: 200; TempCo: 100 ppm/C; EIA_Code: E96; U/M: EA
R116 R117 R126 R127 = CMP-0022900-2: RES, 1.00, 1%, 0.1 W, 0603; Manufacturer: Yageo America; Power_W: 100mW; TempCo: 200 ppm/C; Value_Code: 1R00; U/M: EA; Value: 1.00; EIA_Code: E96; Res_ohm: 1; SizeX_mm: 1.6; SizeY_mm: 0.8; Value2: 0.1W; SizeArea_mm2: 1.28; CompType: Resistor; VDC_V: 150V; AEC Category: Q200
R118-R120 R122 R130-R132 R134 = CRCW08051R00FKEA: RES, 1.00, 1%, 0.125 W, 0805; Manufacturer: Vishay-Dale; CompType: Resistor; Value: 1.00; Res_ohm: 1; Value_Code: 1R00; Power_W: 0.125; Value2: 0.125W; VDC_V: 150; TempCo: 100 ppm/C; EIA_Code: E96; U/M: EA

## Sheet LM5170PowerStage1.SchDoc
size 431 x 279 mm; Date: Not shown in title block; ApprovedBy: Not shown in title block; CheckedBy: Not shown in title block; Author: Not shown in title block; CompanyName: Not shown in title block; Engineer: Not shown in title block; Organization: Not shown in title block; Address1: Not shown in title block; Address2: Not shown in title block; Address3: Not shown in title block; Address4: Not shown in title block; DocumentNumber: 2; Revision: Use project parameter SCH_Rev; SheetNumber: 2; SheetTotal: 9; PageSetup: Record=PageOptions¦CenterHorizontal=True¦CenterVertical=True¦PrintScale=1.00¦XCorrection=1.00¦YCorrection=1.00¦PrintKind=0¦BorderSize=5000000¦LeftOffset=0¦BottomOffset=0¦Orientation=2¦PaperLength=1000¦PaperWidth=1000¦Scale=100¦PaperSource=15¦PrintQuality=600¦MediaType=1¦DitherType=10¦PaperKind=Letter¦PrintScaleMode=1
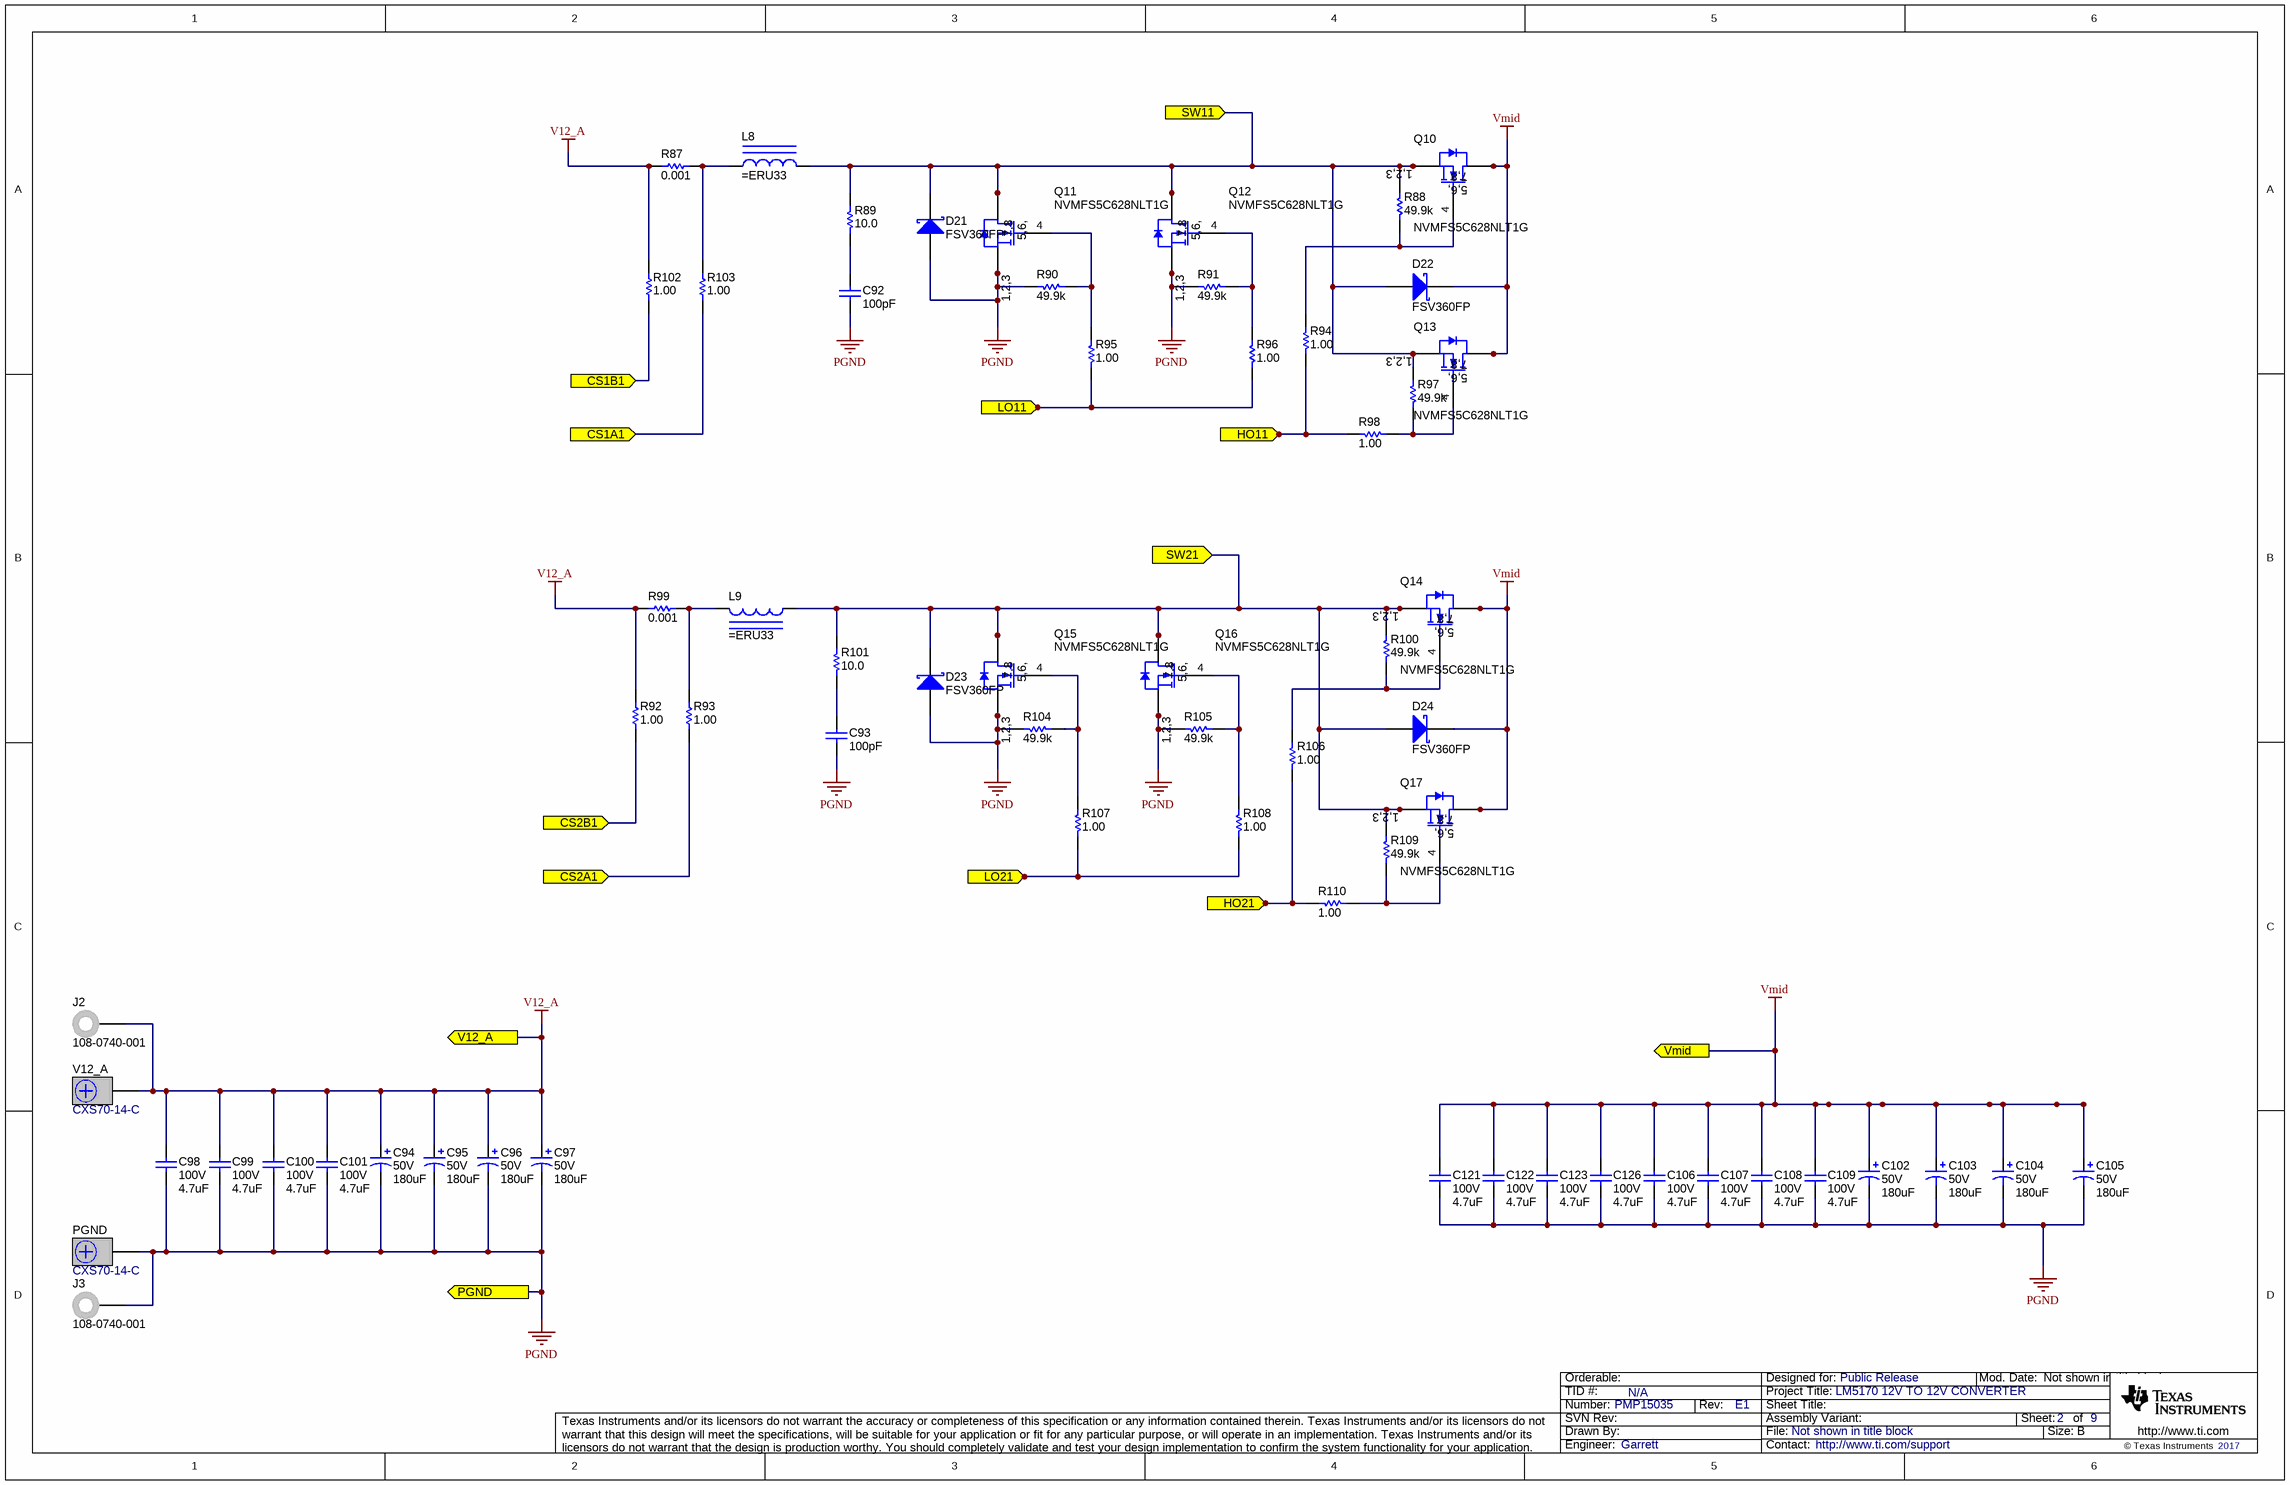
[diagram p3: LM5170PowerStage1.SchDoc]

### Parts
(Parts that share a designator on the sheet are numbered #1, #2 ... from top to bottom, then left to right.)
C92  ValueDisplayed: 100pF  [0805_HV]  (hidden comment: 08051A101KAT2A)
C93  ValueDisplayed: 100pF  [0805_HV]  (hidden comment: 08051A101KAT2A)
C94  VDC_V: 50V  ValueDisplayed: 180uF  [CR_1000x1270]  (hidden comment: PCR1H181MCL1GS)
C95  VDC_V: 50V  ValueDisplayed: 180uF  [CR_1000x1270]  (hidden comment: PCR1H181MCL1GS)
C96  VDC_V: 50V  ValueDisplayed: 180uF  [CR_1000x1270]  (hidden comment: PCR1H181MCL1GS)
C97  VDC_V: 50V  ValueDisplayed: 180uF  [CR_1000x1270]  (hidden comment: PCR1H181MCL1GS)
C98  VDC_V: 100V  ValueDisplayed: 4.7uF  [2220_280]  (hidden comment: C5750X7R2A475M230KA)
C99  VDC_V: 100V  ValueDisplayed: 4.7uF  [2220_280]  (hidden comment: C5750X7R2A475M230KA)
C100  VDC_V: 100V  ValueDisplayed: 4.7uF  [2220_280]  (hidden comment: C5750X7R2A475M230KA)
C101  VDC_V: 100V  ValueDisplayed: 4.7uF  [2220_280]  (hidden comment: C5750X7R2A475M230KA)
C102  VDC_V: 50V  ValueDisplayed: 180uF  [CR_1000x1270]  (hidden comment: PCR1H181MCL1GS)
C103  VDC_V: 50V  ValueDisplayed: 180uF  [CR_1000x1270]  (hidden comment: PCR1H181MCL1GS)
C104  VDC_V: 50V  ValueDisplayed: 180uF  [CR_1000x1270]  (hidden comment: PCR1H181MCL1GS)
C105  VDC_V: 50V  ValueDisplayed: 180uF  [CR_1000x1270]  (hidden comment: PCR1H181MCL1GS)
C106  VDC_V: 100V  ValueDisplayed: 4.7uF  [2220_280]  (hidden comment: C5750X7R2A475M230KA)
C107  VDC_V: 100V  ValueDisplayed: 4.7uF  [2220_280]  (hidden comment: C5750X7R2A475M230KA)
C108  VDC_V: 100V  ValueDisplayed: 4.7uF  [2220_280]  (hidden comment: C5750X7R2A475M230KA)
C109  VDC_V: 100V  ValueDisplayed: 4.7uF  [2220_280]  (hidden comment: C5750X7R2A475M230KA)
C121  VDC_V: 100V  ValueDisplayed: 4.7uF  [2220_280]  (hidden comment: C5750X7R2A475M230KA)
C122  VDC_V: 100V  ValueDisplayed: 4.7uF  [2220_280]  (hidden comment: C5750X7R2A475M230KA)
C123  VDC_V: 100V  ValueDisplayed: 4.7uF  [2220_280]  (hidden comment: C5750X7R2A475M230KA)
C126  VDC_V: 100V  ValueDisplayed: 4.7uF  [2220_280]  (hidden comment: C5750X7R2A475M230KA)
D21  FSV360FP  [SOD-123HE]
D22  FSV360FP  [SOD-123HE]
D23  FSV360FP  [SOD-123HE]
D24  FSV360FP  [SOD-123HE]
J2  108-0740-001  [Johnson_108-0740-001]  (mechanical)
J3  108-0740-001  [Johnson_108-0740-001]  (mechanical)
L8  (no value)  [ERU33]
L9  (no value)  [ERU33]
PGND#2  CXS70-14-C  [Panduit_CXS70-14-C]
Q10  NVMFS5C628NLT1G  [PG-TDSON-8]
Q11  NVMFS5C628NLT1G  [PG-TDSON-8]
Q12  NVMFS5C628NLT1G  [PG-TDSON-8]
Q13  NVMFS5C628NLT1G  [PG-TDSON-8]
Q14  NVMFS5C628NLT1G  [PG-TDSON-8]
Q15  NVMFS5C628NLT1G  [PG-TDSON-8]
Q16  NVMFS5C628NLT1G  [PG-TDSON-8]
Q17  NVMFS5C628NLT1G  [PG-TDSON-8]
R87  ValueDisplayed: 0.001  [CSS2725_001]  (hidden comment: CSS2725FT1L00)
R88  ValueDisplayed: 49.9k  [0603]  (hidden comment: CRCW060349K9FKEA)
R89  ValueDisplayed: 10.0  [1218]  (hidden comment: CRCW121810R0FKEK)
R90  ValueDisplayed: 49.9k  [0603]  (hidden comment: CRCW060349K9FKEA)
R91  ValueDisplayed: 49.9k  [0603]  (hidden comment: CRCW060349K9FKEA)
R92  ValueDisplayed: 1.00  [0603]  (hidden comment: RC0603FR-071RL)
R93  ValueDisplayed: 1.00  [0603]  (hidden comment: RC0603FR-071RL)
R94  ValueDisplayed: 1.00  [0805_HV]  (hidden comment: CRCW08051R00FKEA)
R95  ValueDisplayed: 1.00  [0805_HV]  (hidden comment: CRCW08051R00FKEA)
R96  ValueDisplayed: 1.00  [0805_HV]  (hidden comment: CRCW08051R00FKEA)
R97  ValueDisplayed: 49.9k  [0603]  (hidden comment: CRCW060349K9FKEA)
R98  ValueDisplayed: 1.00  [0805_HV]  (hidden comment: CRCW08051R00FKEA)
R99  ValueDisplayed: 0.001  [CSS2725_001]  (hidden comment: CSS2725FT1L00)
R100  ValueDisplayed: 49.9k  [0603]  (hidden comment: CRCW060349K9FKEA)
R101  ValueDisplayed: 10.0  [1218]  (hidden comment: CRCW121810R0FKEK)
R102  ValueDisplayed: 1.00  [0603]  (hidden comment: RC0603FR-071RL)
R103  ValueDisplayed: 1.00  [0603]  (hidden comment: RC0603FR-071RL)
R104  ValueDisplayed: 49.9k  [0603]  (hidden comment: CRCW060349K9FKEA)
R105  ValueDisplayed: 49.9k  [0603]  (hidden comment: CRCW060349K9FKEA)
R106  ValueDisplayed: 1.00  [0805_HV]  (hidden comment: CRCW08051R00FKEA)
R107  ValueDisplayed: 1.00  [0805_HV]  (hidden comment: CRCW08051R00FKEA)
R108  ValueDisplayed: 1.00  [0805_HV]  (hidden comment: CRCW08051R00FKEA)
R109  ValueDisplayed: 49.9k  [0603]  (hidden comment: CRCW060349K9FKEA)
R110  ValueDisplayed: 1.00  [0805_HV]  (hidden comment: CRCW08051R00FKEA)
V12_A  CXS70-14-C  [Panduit_CXS70-14-C]

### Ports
CS1A1, CS1B1, CS2A1, CS2B1, HO11, HO21, LO11, LO21, PGND, SW11, SW21, V12_A, Vmid

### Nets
PGND: C92.2 C93.2 C94.2(-) C95.2(-) C96.2(-) C97.2(-) C98.2 C99.2 C100.2 C101.2 C102.2(-) C103.2(-) C104.2(-) C105.2(-) C106.2 C107.2 C108.2 C109.2 C121.2 C122.2 C123.2 C126.2 D21.2(A) D23.2(A) J3.1 PGND#2.1 Q11.1(S) Q11.2(S) Q11.3(S) Q12.1(S) Q12.2(S) Q12.3(S) Q15.1(S) Q15.2(S) Q15.3(S) Q16.1(S) Q16.2(S) Q16.3(S) R90.1 R91.1 R104.2 R105.2 ; port PGND
V12_A: C94.1(+) C95.1(+) C96.1(+) C97.1(+) C98.1 C99.1 C100.1 C101.1 J2.1 R87.1 R92.2 R99.1 R102.2 V12_A.1 ; port V12_A
Vmid: C102.1(+) C103.1(+) C104.1(+) C105.1(+) C106.1 C107.1 C108.1 C109.1 C121.1 C122.1 C123.1 C126.1 D22.1(K) D24.1(K) Q10.5(D) Q10.6(D) Q10.7(D) Q10.8(D) Q10.9(D) Q13.5(D) Q13.6(D) Q13.7(D) Q13.8(D) Q13.9(D) Q14.5(D) Q14.6(D) Q14.7(D) Q14.8(D) Q14.9(D) Q17.5(D) Q17.6(D) Q17.7(D) Q17.8(D) Q17.9(D) ; port Vmid
CS1A1: R103.1 ; port CS1A1
CS1B1: R102.1 ; port CS1B1
CS2A1: R93.1 ; port CS2A1
CS2B1: R92.1 ; port CS2B1
HO11: R94.1 R98.1 ; port HO11
HO21: R106.1 R110.1 ; port HO21
LO11: R95.1 R96.1 ; port LO11
LO21: R107.1 R108.1 ; port LO21
SW11: D21.1(K) D22.2(A) L8.2 Q10.1(S) Q10.2(S) Q10.3(S) Q11.5(D) Q11.6(D) Q11.7(D) Q11.8(D) Q11.9(D) Q12.5(D) Q12.6(D) Q12.7(D) Q12.8(D) Q12.9(D) Q13.1(S) Q13.2(S) Q13.3(S) R88.2 R89.2 R97.2 ; port SW11
SW21: D23.1(K) D24.2(A) L9.1 Q14.1(S) Q14.2(S) Q14.3(S) Q15.5(D) Q15.6(D) Q15.7(D) Q15.8(D) Q15.9(D) Q16.5(D) Q16.6(D) Q16.7(D) Q16.8(D) Q16.9(D) Q17.1(S) Q17.2(S) Q17.3(S) R100.2 R101.2 R109.2 ; port SW21
NetC92_1: C92.1 R89.1
NetC93_1: C93.1 R101.1
NetL8_1: L8.1 R87.2 R103.2
NetL9_2: L9.2 R93.2 R99.2
NetQ10_4: Q10.4(G) R88.1 R94.2
NetQ11_4: Q11.4(G) R90.2 R95.2
NetQ12_4: Q12.4(G) R91.2 R96.2
NetQ13_4: Q13.4(G) R97.1 R98.2
NetQ14_4: Q14.4(G) R100.1 R106.2
NetQ15_4: Q15.4(G) R104.1 R107.2
NetQ16_4: Q16.4(G) R105.1 R108.2
NetQ17_4: Q17.4(G) R109.1 R110.2

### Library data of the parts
C92 C93 = 08051A101KAT2A: as C110 on sheet LM5170PowerStage2
C94-C97 C102-C105 = CMP-0012273-3: as C112 on sheet LM5170PowerStage2
C98-C101 C106-C109 C121-C123 C126 = CMP-0009385-2: as C116 on sheet LM5170PowerStage2
D21-D24 = CMP-0028825-1: as D25 on sheet LM5170PowerStage2
J2 J3 = 108-0740-001: as J4 on sheet LM5170PowerStage2
L8 L9 = ERU33: as L10 on sheet LM5170PowerStage2
PGND#2 V12_A = CXS70-14-C: as PGND#1 on sheet LM5170PowerStage2
Q10-Q17 = NVMFS5C628NLT1G: as Q18 on sheet LM5170PowerStage2
R87 R99 = CMP-0015025-2: as R111 on sheet LM5170PowerStage2
R88 R90 R91 R97 R100 R104 R105 R109 = CRCW080549K9FKEA: RES, 49.9 k, 1%, 0.125 W, 0805; Manufacturer: Vishay-Dale; CompType: Resistor; Value: 49.9k; Res_ohm: 49900; Value_Code: 49k9; Tolerance_%: 1; Power_W: 0.125; Value2: 0.125W; VDC_V: 150; TempCo: 100 ppm/C; EIA_Code: E96; U/M: EA
R89 R101 = CRCW121810R0FKEK: as R113 on sheet LM5170PowerStage2
R92 R93 R102 R103 = CMP-0022900-2: as R116 on sheet LM5170PowerStage2
R94-R96 R98 R106-R108 R110 = CRCW08051R00FKEA: as R118 on sheet LM5170PowerStage2

## Sheet AnalogControl1.SchDoc
size 431 x 279 mm; Date: Not shown in title block; ApprovedBy: Not shown in title block; CheckedBy: Not shown in title block; Author: Not shown in title block; CompanyName: Not shown in title block; Engineer: Not shown in title block; Organization: Not shown in title block; Address1: Not shown in title block; Address2: Not shown in title block; Address3: Not shown in title block; Address4: Not shown in title block; DocumentNumber: 6; Revision: Use project parameter SCH_Rev; SheetNumber: 6; SheetTotal: 9; PageSetup: Record=PageOptions¦CenterHorizontal=True¦CenterVertical=True¦PrintScale=1.00¦XCorrection=1.00¦YCorrection=1.00¦PrintKind=0¦BorderSize=5000000¦LeftOffset=0¦BottomOffset=0¦Orientation=2¦PaperLength=1000¦PaperWidth=1000¦Scale=100¦PaperSource=15¦PrintQuality=600¦MediaType=1¦DitherType=10¦PaperKind=Letter¦PrintScaleMode=1
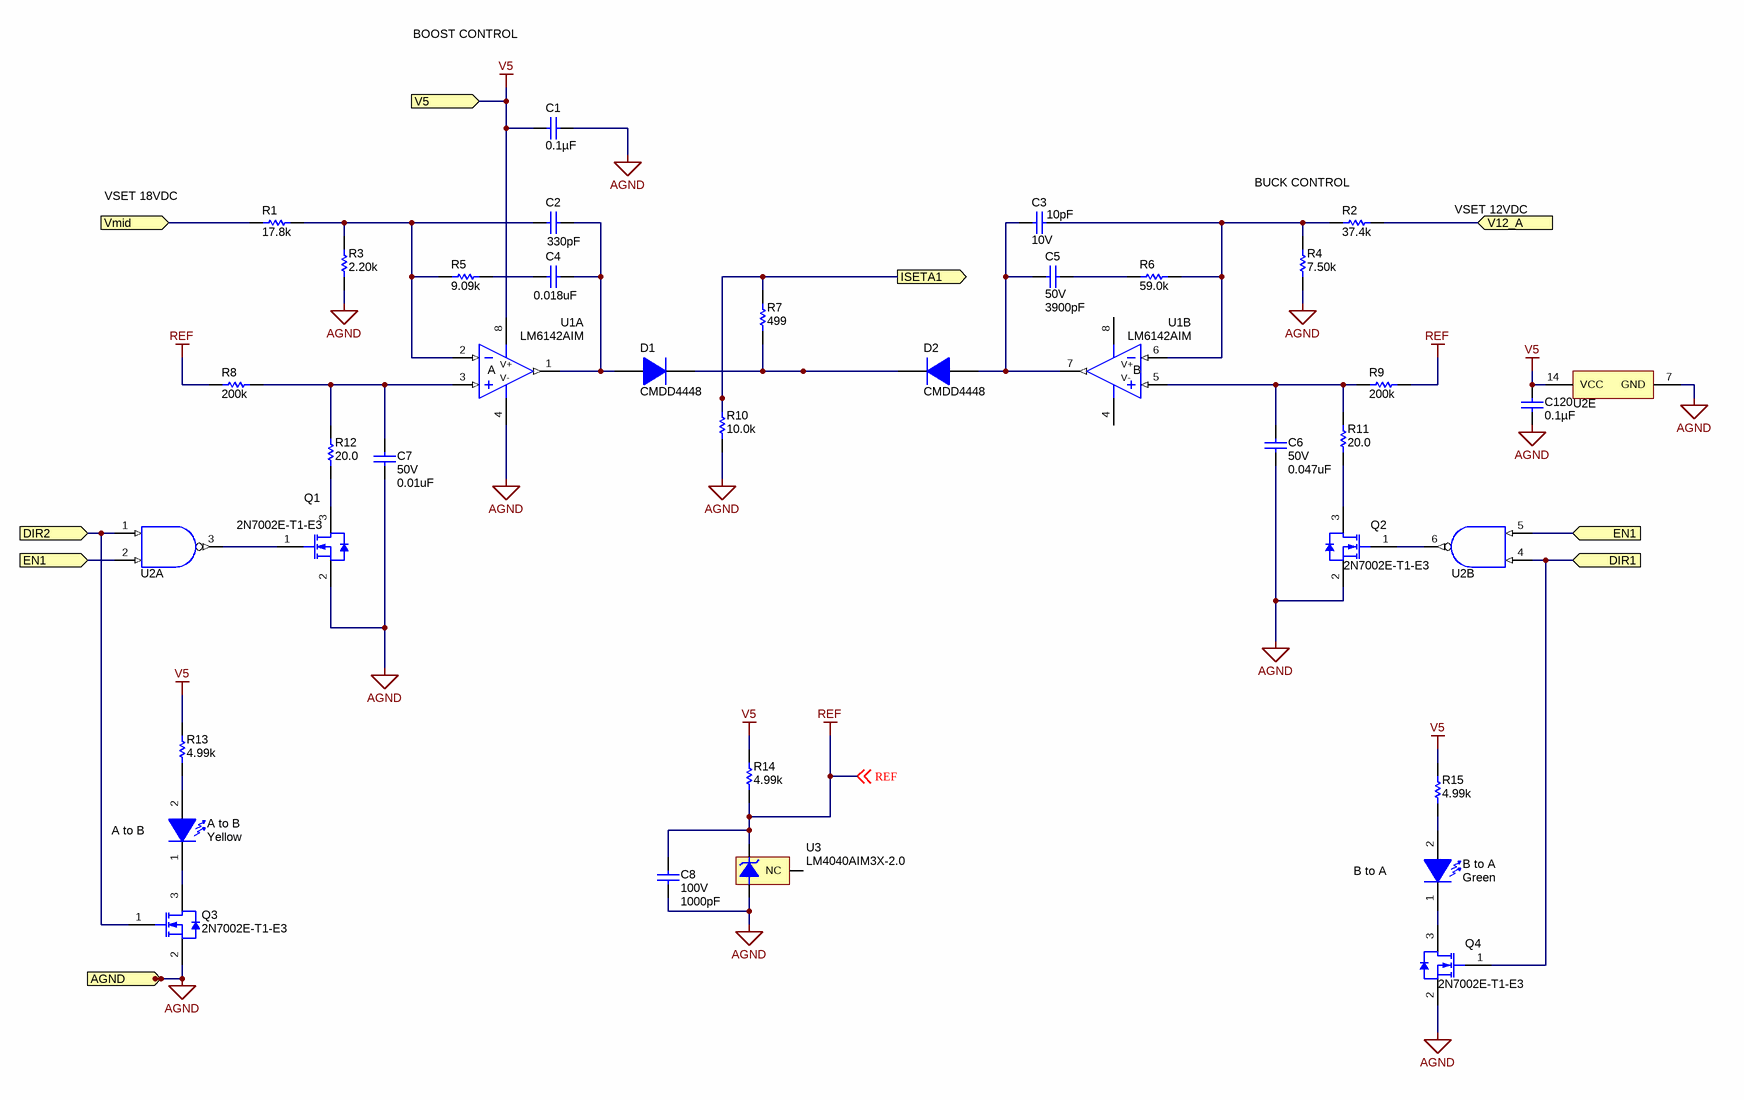
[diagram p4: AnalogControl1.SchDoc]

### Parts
A_to_B  value Yellow  [WL-SMCW_YELLOW]  (hidden comment: 150060YS75000)
B_to_A  value Green  [WL-SMCW_GREEN]  (hidden comment: 150060VS75000)
C1  ValueDisplayed: 0.1µF  [0603L]  (hidden comment: GRM188R72A104KA35D)
C2  ValueDisplayed: 330pF  [0603]  (hidden comment: C0603C331J5GACTU)
C3  VDC_V: 10V  ValueDisplayed: 10pF  [0603]  (hidden comment: 0603ZC100KAT2A)
C4  ValueDisplayed: 0.018uF  [0603]  (hidden comment: GRM188R71H183KA01D)
C5  VDC_V: 50V  ValueDisplayed: 3900pF  [0603]  (hidden comment: GRM188R71H392KA01D)
C6  VDC_V: 50V  ValueDisplayed: 0.047uF  [0805_HV]  (hidden comment: 08055C473KAT2A)
C7  VDC_V: 50V  ValueDisplayed: 0.01uF  [0805_HV]  (hidden comment: 885012207092)
C8  VDC_V: 100V  ValueDisplayed: 1000pF  [0603L]  (hidden comment: C1608C0G2A102J080AA)
C120  ValueDisplayed: 0.1µF  [0603L]  (hidden comment: GRM188R72A104KA35D)
D1  CMDD4448  [sod-323]
D2  CMDD4448  [sod-323]
Q1  2N7002E-T1-E3  [SOT-23]
Q2  2N7002E-T1-E3  [SOT-23]
Q3  2N7002E-T1-E3  [SOT-23]
Q4  2N7002E-T1-E3  [SOT-23]
R1  ValueDisplayed: 17.8k  [0603L]  (hidden comment: RC0603FR-0717K8L)
R2  ValueDisplayed: 37.4k  [0603L]  (hidden comment: CRCW060337K4FKEA)
R3  ValueDisplayed: 2.20k  [0603]  (hidden comment: RC0603FR-072K2L)
R4  ValueDisplayed: 7.50k  [0603]  (hidden comment: RC0603FR-077K5L)
R5  ValueDisplayed: 9.09k  [0603]  (hidden comment: RC0603FR-079K09L)
R6  ValueDisplayed: 59.0k  [0603]  (hidden comment: RC0603FR-0759KL)
R7  ValueDisplayed: 499  [0603]  (hidden comment: RC0603FR-07499RL)
R8  ValueDisplayed: 200k  [0603]  (hidden comment: RC0603FR-07200KL)
R9  ValueDisplayed: 200k  [0603]  (hidden comment: RC0603FR-07200KL)
R10  ValueDisplayed: 10.0k  [0603L]  (hidden comment: CRCW060310K0FKEA)
R11  ValueDisplayed: 20.0  [0603L]  (hidden comment: CRCW060320R0FKEA)
R12  ValueDisplayed: 20.0  [0603L]  (hidden comment: CRCW060320R0FKEA)
R13  ValueDisplayed: 4.99k  [0603L]  (hidden comment: CRCW06034K99FKEA)
R14  ValueDisplayed: 4.99k  [0603L]  (hidden comment: CRCW06034K99FKEA)
R15  ValueDisplayed: 4.99k  [0603L]  (hidden comment: CRCW06034K99FKEA)
U1  LM6142AIM  [D0008A_N]  (parts A,B of 2)
U2  SN74LV00ADR  [D0014A_N]  (value not drawn)  (parts A,B,E of 5)
U3  LM4040AIM3X-2.0  [MF03A_N]

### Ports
AGND, DIR1, DIR2, EN1, ISETA1, V5, V12_A, Vmid

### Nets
AGND: C1.2 C6.2 C7.2 C8.2 C120.2 Q1.2(S) Q2.2(S) Q3.2(S) Q4.2(S) R3.1 R4.1 R10.2 U1.4(V-) U2.7(GND) U3.2(-V) ; port AGND
DIR1: Q4.1(G) U2.4(2A) ; port DIR1
EN1: U2.2(1B) U2.5(2B) ; port EN1
REF: C8.1 R8.2 R9.1 R14.2 U3.1(+V) ; off-sheet REF
V5: C1.1 C120.1 R13.1 R14.1 R15.1 U1.8(V+) U2.14(VCC) ; port V5
V12_A: R2.2 ; port V12_A
Vmid: R1.1 ; port Vmid
DIR2: Q3.1(G) U2.1(1A) ; port DIR2
ISETA1: R7.2 R10.1 ; port ISETA1
NetA_to_B_1: A_to_B.1(K) Q3.3(D)
NetA_to_B_2: A_to_B.2(A) R13.2
NetB_to_A_1: B_to_A.1(K) Q4.3(D)
NetB_to_A_2: B_to_A.2(A) R15.2
NetC2_1: C2.1 C4.1 D1.2(A) U1.1(OUT)
NetC2_2: C2.2 R1.2 R3.2 R5.2 U1.2(IN-)
NetC3_1: C3.1 R2.1 R4.2 R6.1 U1.6(IN-)
NetC3_2: C3.2 C5.1 D2.2(A) U1.7(OUT)
NetC4_2: C4.2 R5.1
NetC5_2: C5.2 R6.2
NetC6_1: C6.1 R9.2 R11.2 U1.5(IN+)
NetC7_1: C7.1 R8.1 R12.2 U1.3(IN+)
NetD1_1: D1.1(K) D2.1(K) R7.1
NetQ1_1: Q1.1(G) U2.3(1Y)
NetQ1_3: Q1.3(D) R12.1
NetQ2_1: Q2.1(G) U2.6(2Y)
NetQ2_3: Q2.3(D) R11.1

Not connected (* = marked no-connect by the designer): U3 3(NC)

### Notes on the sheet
- BOOST CONTROL
- VSET 18VDC
- (near R2) BUCK CONTROL
- VSET 12VDC
- (near A_to_B) A to B
- (near B_to_A) B to A

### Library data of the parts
A_to_B = 150060YS75000: LED, Yellow, SMD; Manufacturer: Wurth Elektronik; Vf_V: 2; Value2: 2V; Io_A: 0.02; Value1: W; U/M: EA
B_to_A = 150060VS75000: LED, Green, SMD; Manufacturer: Wurth Elektronik; Vf_V: 2; Value2: 2V; Io_A: 0.02; Value1: W; U/M: EA
C1 C120 = GRM188R72A104KA35D: as C9 on sheet AnalogControl2
C2 = CMP-0006920-4: as C11 on sheet AnalogControl2
C3 = CMP-0006811-4: as C10 on sheet AnalogControl2
C4 = CMP-0007440-5: as C13 on sheet AnalogControl2
C5 = CMP-0007453-4: as C12 on sheet AnalogControl2
C6 = CMP-0007659-2: as C15 on sheet AnalogControl2
C7 = CMP-0007694-2: as C14 on sheet AnalogControl2
C8 = CMP-0006993-4: CAP, CERM, 1000 pF, 100 V, +/- 5%, C0G/NP0, 0603; Manufacturer: TDK; TaMin_C: -55°C; ESR_ohm: 0.0589; Polarized: N; SizeAreaWB_mm2: 4.68; Value1: 0.0589 ohm; U/M: EA; Value: 1000pF; TaMax_C: 125°C; SizeZ_mm: 1; SizeX_mm: 1.6; SizeY_mm: 0.8; Cap_Case: 0603; SizeArea_mm2: 1.28; CompType: Capacitor; Cap_F: 1nF; AEC Category: Q200
D1 D2 = CMDD4448: as D5 on sheet AnalogControl2
Q1-Q4 = 2N7002E-T1-E3: as Q5 on sheet AnalogControl2
R1 = CMP-0022841-3: as R17 on sheet AnalogControl2
R2 = CMP-0022360-3: as R16 on sheet AnalogControl2
R3 = CMP-0022986-3: as R19 on sheet AnalogControl2
R4 = CMP-0023279-3: as R18 on sheet AnalogControl2
R5 = CMP-0023332-3: as R21 on sheet AnalogControl2
R6 = CMP-0023195-3: as R20 on sheet AnalogControl2
R7 = CMP-0023141-3: as R22 on sheet AnalogControl2
R8 R9 = CMP-0022901-2: as R23 on sheet AnalogControl2
R10 = CRCW060310K0FKEA: as R25 on sheet AnalogControl2
R11 R12 = CRCW060320R0FKEA: as R27 on sheet AnalogControl2
R13-R15 = CRCW06034K99FKEA: RES, 4.99 k, 1%, 0.1 W, 0603; Manufacturer: Vishay-Dale; CompType: Resistor; Value: 4.99k; Res_ohm: 4990; Value_Code: 4k99; Tolerance_%: 1; Power_W: 0.1; Value2: 0.1W; VDC_V: 75; TempCo: 100 ppm/C; EIA_Code: E96; U/M: EA
U1 = LM6142AIM: as U4 on sheet AnalogControl2
U2 = CMP-0052884-1: as U2 on sheet AnalogControl2
U3 = LM4040AIM3X-2.0: Precision Micropower Shunt Voltage Reference, 3-pin SOT-23; Manufacturer: Texas Instruments; PackageTopMarking: RJA*XTT; PowerWise: N; CompType: Voltage Reference IC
